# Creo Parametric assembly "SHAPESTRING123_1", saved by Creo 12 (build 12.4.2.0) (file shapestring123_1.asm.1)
Units: Custom; MM, KILOGRAM, SECS

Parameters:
  PTC_WM_ITERATION = "0"
  PTC_WM_VERSION = "-.0"
  PTC_WM_LIFECYCLE_STATE = "In Work"
  PTC_WM_LIFECYCLE = "MO_CADDocument"
  PTC_WM_CREATED_BY = "Maximilian Roepper (Z0017RMS: MO)"
  PTC_WM_CREATED_ON = "18-Sep-26 11:36:42 AM"
  PTC_WM_MODIFIED_BY = "Maximilian Roepper (Z0017RMS: MO)"
  PTC_WM_MODIFIED_ON = "18-Sep-26 11:36:46 AM"
  PDMLINKNUMBER = "PDM000071454842"
  PTC_WM_NUMBER = "PDM000071454842"

Other parameters: WEIGHT, WEIGHT_FACTOR, WEIGHT_ADD, MC_ERRORS, SUPPLIER

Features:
  1. coordinate system
  2. imported feature
  3. component "SHAPESTRING070_1"
  4. component "SHAPESTRING119_1"
  5. component "SHAPESTRING120_1"
  6. component "SHAPESTRING121_1"
  7. component "SHAPESTRING122_1"

Other named items: DRW_VIEW_ORG, ROUGH-GROB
